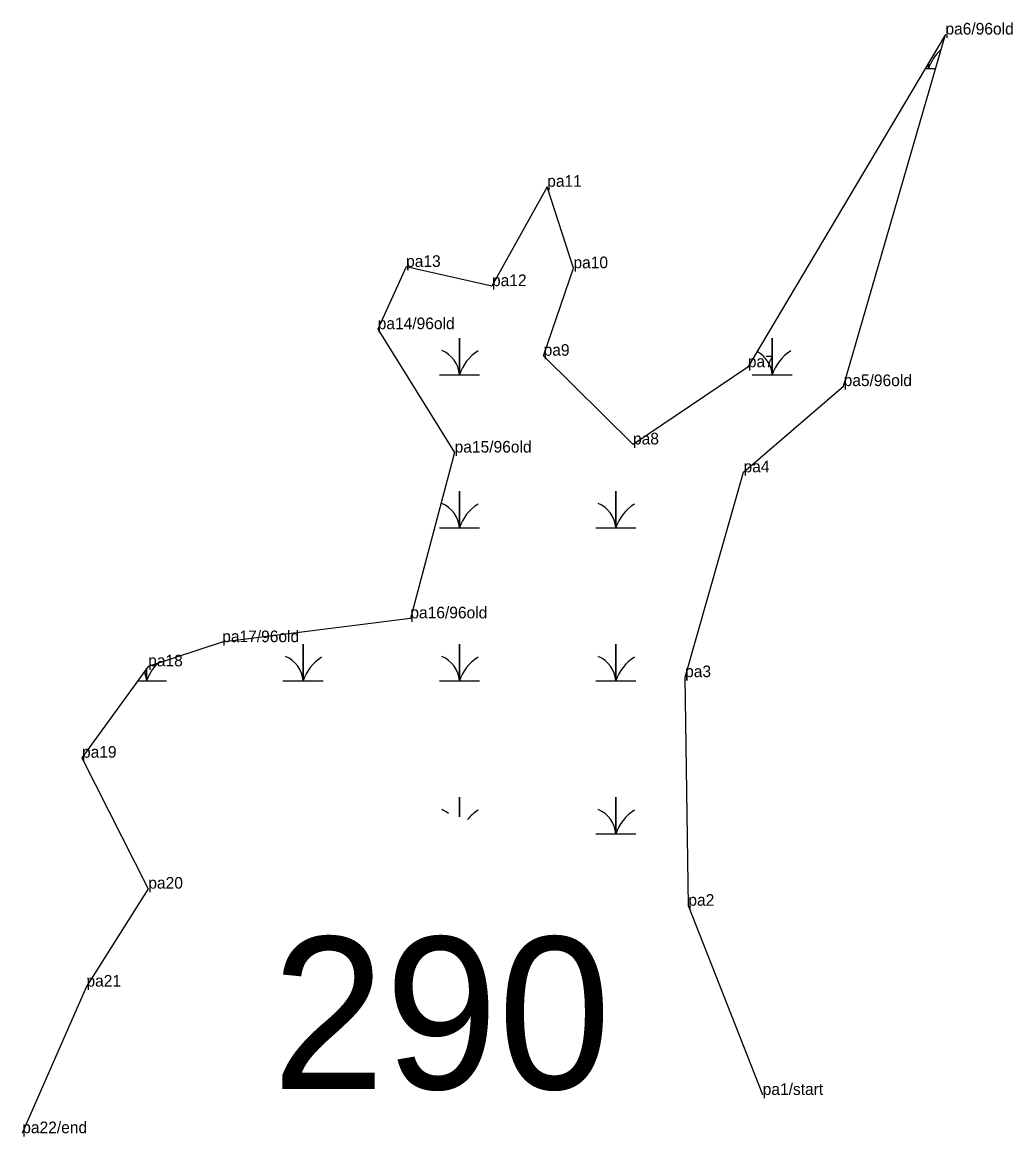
# Model space of a CAD drawing. Extents: x 2072529 to 2268796, y 436423 to 470406.
# Drawn here: x 2250300 to 2250725.9, y 437481.6 to 437960.7 of the extents above; entities that cross this region are included whole.
import ezdxf

# ---------------------------------------------------------------- set-up
doc = ezdxf.new("R2010")
doc.units = 0
for name, color, linetype in [('Default', 7, 'Continuous'), ('Exist Environmental Wetland Boundary', 7, 'Continuous'), ('Exist Environmental Wetland Boundary Cogo Comment', 7, 'Continuous'), ('Exist Hydro Swamp or Marsh', 7, 'Continuous'), ('Old_Level_20', 7, 'Continuous')]:
    doc.layers.add(name, color=color, linetype=linetype)

msp = doc.modelspace()

# ---------------------------------------------------------------- linework, layer by layer
at = {"layer": 'Exist Environmental Wetland Boundary'}
msp.add_lwpolyline([(2250618.39, 437499.58), (2250586.42, 437580.9), (2250585.02, 437679.17), (2250610.14, 437767.23), (2250653.2, 437804.29), (2250696.96, 437955.41), (2250611.99, 437812.4), (2250562.62, 437779.2), (2250524.18, 437817.34), (2250537.01, 437854.96), (2250525.72, 437889.97), (2250501.97, 437847.27), (2250465.04, 437855.51), (2250452.83, 437828.76), (2250485.91, 437775.71), (2250466.87, 437704.45), (2250385.96, 437694.22), (2250354.12, 437683.81), (2250325.66, 437644.54), (2250354.19, 437588.25), (2250327.58, 437546.15), (2250299.98, 437483.14)], dxfattribs=at)
at = {"layer": 'Exist Hydro Swamp or Marsh'}
for points in [[(2250688.26, 437940.76), (2250689.71, 437940.76), (2250689.71, 437943.19)], [(2250689.71, 437943.19), (2250689.71, 437940.76), (2250692.72, 437940.76)], [(2250479.35, 437809.16), (2250487.96, 437809.16), (2250487.96, 437824.94), (2250487.96, 437809.16), (2250496.56, 437809.16)], [(2250613.85, 437809.16), (2250622.46, 437809.16), (2250622.46, 437824.94), (2250622.46, 437809.16), (2250631.06, 437809.16)], [(2250479.35, 437743.36), (2250487.96, 437743.36), (2250487.96, 437759.14), (2250487.96, 437743.36), (2250496.56, 437743.36)], [(2250546.6, 437743.36), (2250555.21, 437743.36), (2250555.21, 437759.14), (2250555.21, 437743.36), (2250563.81, 437743.36)], [(2250412.1, 437677.56), (2250420.71, 437677.56), (2250420.71, 437693.34), (2250420.71, 437677.56), (2250429.31, 437677.56)], [(2250479.35, 437677.56), (2250487.96, 437677.56), (2250487.96, 437693.34), (2250487.96, 437677.56), (2250496.56, 437677.56)], [(2250546.6, 437677.56), (2250555.21, 437677.56), (2250555.21, 437693.34), (2250555.21, 437677.56), (2250563.81, 437677.56)], [(2250349.58, 437677.56), (2250353.46, 437677.56), (2250353.46, 437682.9)], [(2250353.46, 437682.9), (2250353.46, 437677.56), (2250362.06, 437677.56)], [(2250487.96, 437619.1), (2250487.96, 437627.54), (2250487.96, 437619.1)], [(2250546.6, 437611.76), (2250555.21, 437611.76), (2250555.21, 437627.54), (2250555.21, 437611.76), (2250563.81, 437611.76)]]:
    msp.add_lwpolyline(points, dxfattribs=at)
for centre, radius, start, end in [((2250707.95, 437934.7), 19.22, 131.9067, 161.6222), ((2250677.44, 437939.87), 12.3, 4.1403, 13.2818), ((2250475.69, 437808.27), 12.3, 4.1403, 67.535), ((2250506.2, 437803.1), 19.22, 122.1274, 161.6222), ((2250610.19, 437808.27), 12.3, 4.1403, 61.9103), ((2250640.7, 437803.1), 19.22, 122.1274, 161.6222), ((2250475.69, 437742.47), 12.3, 4.1403, 67.535), ((2250506.2, 437737.3), 19.22, 122.1274, 161.6222), ((2250542.94, 437742.47), 12.3, 4.1403, 67.535), ((2250573.45, 437737.3), 19.22, 122.1274, 161.6222), ((2250408.44, 437676.67), 12.3, 4.1403, 67.535), ((2250438.95, 437671.5), 19.22, 122.1274, 161.6222), ((2250475.69, 437676.67), 12.3, 4.1403, 67.535), ((2250506.2, 437671.5), 19.22, 122.1274, 161.6222), ((2250542.94, 437676.67), 12.3, 4.1403, 67.535), ((2250573.45, 437671.5), 19.22, 122.1274, 161.6222), ((2250371.7, 437671.5), 19.22, 134.8204, 161.6222), ((2250341.19, 437676.67), 12.3, 4.1403, 23.3894), ((2250475.69, 437610.87), 12.3, 51.6874, 67.535), ((2250506.2, 437605.7), 19.22, 122.1274, 140.0583), ((2250542.94, 437610.87), 12.3, 4.1403, 67.535), ((2250573.45, 437605.7), 19.22, 122.1274, 161.6222)]:
    msp.add_arc(centre, radius, start, end, dxfattribs=at)
at = {"layer": 'Old_Level_20'}
for p, q in [((2250696.96, 437955.41), (2250696.96, 437955.41)), ((2250525.72, 437889.97), (2250525.72, 437889.97)), ((2250465.04, 437855.51), (2250465.04, 437855.51)), ((2250537.01, 437854.96), (2250537.01, 437854.96)), ((2250501.97, 437847.27), (2250501.97, 437847.27)), ((2250452.83, 437828.76), (2250452.83, 437828.76)), ((2250524.18, 437817.34), (2250524.18, 437817.34)), ((2250611.99, 437812.4), (2250611.99, 437812.4)), ((2250653.2, 437804.29), (2250653.2, 437804.29)), ((2250562.62, 437779.2), (2250562.62, 437779.2)), ((2250485.91, 437775.71), (2250485.91, 437775.71)), ((2250610.14, 437767.23), (2250610.14, 437767.23)), ((2250466.87, 437704.45), (2250466.87, 437704.45)), ((2250385.96, 437694.22), (2250385.96, 437694.22)), ((2250354.12, 437683.81), (2250354.12, 437683.81)), ((2250585.02, 437679.17), (2250585.02, 437679.17)), ((2250325.66, 437644.54), (2250325.66, 437644.54)), ((2250354.19, 437588.25), (2250354.19, 437588.25)), ((2250586.42, 437580.9), (2250586.42, 437580.9)), ((2250327.58, 437546.15), (2250327.58, 437546.15)), ((2250618.39, 437499.58), (2250618.39, 437499.58)), ((2250299.98, 437483.14), (2250299.98, 437483.14))]:
    msp.add_line(p, q, dxfattribs=at)

# ---------------------------------------------------------------- texts
at = {"layer": 'Default'}
msp.add_text('290', height=65.34, dxfattribs=at).set_placement((2250407.37, 437502.13))
at = {"layer": 'Exist Environmental Wetland Boundary Cogo Comment'}
for s, p in [('pa6/96old', (2250696.96, 437955.41)), ('pa11', (2250525.72, 437889.97)), ('pa13', (2250465.04, 437855.51)), ('pa10', (2250537.01, 437854.96)), ('pa12', (2250501.97, 437847.27)), ('pa14/96old', (2250452.83, 437828.76)), ('pa9', (2250524.18, 437817.34)), ('pa7', (2250611.99, 437812.4)), ('pa5/96old', (2250653.2, 437804.29)), ('pa8', (2250562.62, 437779.2)), ('pa15/96old', (2250485.91, 437775.71)), ('pa4', (2250610.14, 437767.23)), ('pa16/96old', (2250466.87, 437704.45)), ('pa17/96old', (2250385.96, 437694.22)), ('pa18', (2250354.12, 437683.81)), ('pa3', (2250585.02, 437679.17)), ('pa19', (2250325.66, 437644.54)), ('pa20', (2250354.19, 437588.25)), ('pa2', (2250586.42, 437580.9)), ('pa21', (2250327.58, 437546.15)), ('pa1/start', (2250618.39, 437499.58)), ('pa22/end', (2250299.98, 437483.14))]:
    msp.add_text(s, height=5, dxfattribs=at).set_placement(p)

doc.saveas('drawing.dxf')
